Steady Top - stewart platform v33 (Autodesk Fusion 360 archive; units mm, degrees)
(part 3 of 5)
sketch "Sketch39" plane through (0, 0, 60.538) normal (0, 0, -1) x axis (1, 0, 0)
  curve K1 (-57.6704, 6.1748) -> (-51.1363, 4.8016)
  line L1 (-50.8174, 2.2182) -> (-57.6704, 6.1748)
  line L2 (-23.4876, -45.1182) -> (-50.8174, 2.2182)
  line L3 (-23.4876, -53.0314) -> (-23.4876, -45.1182)
  curve K2 (-21.4098, -46.6861) -> (-23.4876, -53.0314)
  curve K3 (-21.4098, -46.6861) -> (21.4098, -46.6861)
  curve K4 (23.4876, -53.0314) -> (21.4098, -46.6861)
  line L4 (23.4876, -45.1182) -> (23.4876, -53.0314)
  line L5 (50.8174, 2.2182) -> (23.4876, -45.1182)
  line L6 (57.6704, 6.1748) -> (50.8174, 2.2182)
  curve K5 (51.1363, 4.8016) -> (57.6704, 6.1748)
  curve K6 (51.1363, 4.8016) -> (28.8711, 42.469)
  curve K7 (28.8711, 42.469) -> (33.2215, 47.543)
  curve K8 (33.2215, 47.543) -> (34.8563, 49.4246)
  line L7 (-34.0436, 49.4926) -> (34.0436, 49.4926)
  curve K9 (-34.8563, 49.4246) -> (-33.2215, 47.543)
  line L8 (19.9564, 46.6037) -> (-34.0436, 46.6037)
  line L9 (21.9564, -34.3963) -> (21.9564, 44.6037)
  line L10 (-9.0436, -36.3963) -> (19.9564, -36.3963)
  line L11 (-11.0436, -20.9963) -> (-11.0436, -34.3963)
  line L12 (-31.0436, -18.3963) -> (-13.6436, -18.3963)
  line L13 (-33.0436, 2.6037) -> (-33.0436, -16.3963)
  line L14 (-11.6436, 4.6037) -> (-31.0436, 4.6037)
  line L15 (-9.0436, 11.0037) -> (-9.0436, 7.2037)
  line L16 (-34.0436, 13.6037) -> (-11.6436, 13.6037)
  line L17 (-36.0436, 36.6685) -> (-36.0436, 15.6037)
  curve K10 (-36.0436, 36.6685) -> (-51.1363, 4.8016)
  line L18 (-32.1129, 44.8573) -> (-36.65, 41.1209)
  line L19 (-7.0436, 45.9249) -> (-32.1129, 44.8573)
  line L20 (15.1267, 40.5871) -> (-7.0436, 45.9249)
  line L21 (21.9564, 13.0084) -> (15.1267, 40.5871)
  line L22 (27.9374, 13.0084) -> (21.9564, 13.0084)
  line L23 (27.3147, 47.8821) -> (27.9374, 13.0084)
  line L24 (-36.2006, 47.543) -> (27.3147, 47.8821)
  line L25 (-38.5136, 43.2045) -> (-36.2006, 47.543)
  line L26 (-36.65, 41.1209) -> (-38.5136, 43.2045)
  line L27 (11.3178, -29.1242) -> (19.9331, 23.7985)
  line L28 (-0.6206, -29.1242) -> (11.3178, -29.1242)
  line L29 (-11.8052, -19.1578) -> (-0.6206, -29.1242)
  arc A1 centre (34.0436, 44.6037) radius 4.8889 clockwise from (34.0436, 49.4926) to (34.8563, 49.4246)
  arc A2 centre (-34.0436, 44.6037) radius 4.8889 clockwise from (-34.8563, 49.4246) to (-34.0436, 49.4926)
  arc A3 centre (0, 0) radius 58 clockwise from (-34.656, 46.5076) to (-33.2215, 47.543)
  arc A4 centre (-34.0436, 44.6037) radius 2 clockwise from (-34.656, 46.5076) to (-34.0436, 46.6037)
  arc A5 centre (19.9564, 44.6037) radius 2 clockwise from (19.9564, 46.6037) to (21.9564, 44.6037)
  arc A6 centre (19.9564, -34.3963) radius 2 clockwise from (21.9564, -34.3963) to (19.9564, -36.3963)
  arc A7 centre (-9.0436, -34.3963) radius 2 clockwise from (-9.0436, -36.3963) to (-11.0436, -34.3963)
  arc A8 centre (-13.6436, -20.9963) radius 2.6 clockwise from (-13.6436, -18.3963) to (-11.0436, -20.9963)
  arc A9 centre (-31.0436, -16.3963) radius 2 clockwise from (-31.0436, -18.3963) to (-33.0436, -16.3963)
  arc A10 centre (-31.0436, 2.6037) radius 2 clockwise from (-33.0436, 2.6037) to (-31.0436, 4.6037)
  arc A11 centre (-11.6436, 7.2037) radius 2.6 clockwise from (-9.0436, 7.2037) to (-11.6436, 4.6037)
  arc A12 centre (-11.6436, 11.0037) radius 2.6 clockwise from (-11.6436, 13.6037) to (-9.0436, 11.0037)
  arc A13 centre (-34.0436, 15.6037) radius 2 clockwise from (-34.0436, 13.6037) to (-36.0436, 15.6037)
  point P58 (21.9564, 13.0084)
  point P66 (-11.8052, -19.1578)
  coincident L9 P58
  perpendicular L9 L22
  perpendicular L9 L28
  midpoint A8 P66
extrude "Extrude33" add sketch "Sketch39" profile of K9 A3 A4 L8 A5 L9 A6 L10 A7 L11 A8 L18 L19 L20 L21 L24 L25 L26 L27 L28 L29 against normal blind 2.5
component_insert "Component Insert19"
sketch "Sketch40" plane through (0, 0, -18.75) normal (0, 0, -1) x axis (1, 0, 0)
  line L1 (-50.6551, -0.2628) -> (-40.5926, -17.6915)
  line L2 (-41.6918, 4.9122) -> (-50.6551, -0.2628)
  line L3 (-31.6293, -12.5165) -> (-41.6918, 4.9122)
  line L4 (-40.5926, -17.6915) -> (-31.6293, -12.5165)
  line L5 (-26.6543, -21.1335) -> (-35.6176, -26.3085)
  line L6 (-16.5918, -38.5622) -> (-26.6543, -21.1335)
  line L7 (-25.5551, -43.7372) -> (-16.5918, -38.5622)
  line L8 (-35.6176, -26.3085) -> (-25.5551, -43.7372)
  line L9 (-4.975, 44) -> (-25.1, 44)
  line L10 (-4.975, 33.65) -> (-4.975, 44)
  line L11 (-25.1, 33.65) -> (-4.975, 33.65)
  line L12 (-25.1, 44) -> (-25.1, 33.65)
  line L13 (25.1, 44) -> (4.975, 44)
  line L14 (25.1, 33.65) -> (25.1, 44)
  line L15 (4.975, 33.65) -> (25.1, 33.65)
  line L16 (4.975, 44) -> (4.975, 33.65)
  line L17 (-9.7616, -40.3924) -> (-16.0102, -44)
  line L18 (-39.8616, 11.7424) -> (-9.7616, -40.3924)
  line L19 (-46.1102, 8.1347) -> (-39.8616, 11.7424)
  line L20 (-30.1, 35.8653) -> (-46.1102, 8.1347)
  line L21 (-30.1, 28.65) -> (-30.1, 35.8653)
  line L22 (30.1, 28.65) -> (-30.1, 28.65)
  line L23 (30.1, 35.8653) -> (30.1, 28.65)
  line L24 (46.1102, 8.1347) -> (30.1, 35.8653)
  line L25 (39.8616, 11.7424) -> (46.1102, 8.1347)
  line L26 (9.7616, -40.3924) -> (39.8616, 11.7424)
  line L27 (16.0102, -44) -> (9.7616, -40.3924)
  line L28 (-16.0102, -44) -> (16.0102, -44)
  line L29 (40.5926, -17.6915) -> (50.6551, -0.2628)
  line L30 (31.6293, -12.5165) -> (40.5926, -17.6915)
  line L31 (41.6918, 4.9122) -> (31.6293, -12.5165)
  line L32 (50.6551, -0.2628) -> (41.6918, 4.9122)
  line L33 (16.5918, -38.5622) -> (25.5551, -43.7372)
  line L34 (26.6543, -21.1335) -> (16.5918, -38.5622)
  line L35 (35.6176, -26.3085) -> (26.6543, -21.1335)
  line L36 (25.5551, -43.7372) -> (35.6176, -26.3085)
  line L37 (78.9466, 12.9395) -> (28.2673, -74.8395)
  line L38 (-50.6793, 61.9) -> (50.6793, 61.9)
  line L39 (-28.2673, -74.8395) -> (-78.9466, 12.9395)
  line L40 (121.7393, 0) -> (-121.7393, 0)
  line L41 (121.7393, 253.3747) -> (121.7393, 0)
  line L42 (-121.7393, 253.3747) -> (121.7393, 253.3747)
  line L43 (-121.7393, 0) -> (-121.7393, 253.3747)
  line L44 (121.7393, 253.3747) -> (-121.7393, 0)
  line L45 (-121.7393, 253.3747) -> (121.7393, 0)
  line L46 (41.9005, 165.7123) -> (-23.0995, 165.7123)
  arc A1 centre (0, 0) radius 80 clockwise from (28.2673, -74.8395) to (-28.2673, -74.8395)
  arc A2 centre (0, 0) radius 80 clockwise from (50.6793, 61.9) to (78.9466, 12.9395)
  arc A3 centre (0, 0) radius 80 clockwise from (-78.9466, 12.9395) to (-50.6793, 61.9)
  circle C1 centre (0, 0) radius 121.7393
  circle C2 centre (-23.0995, 165.7123) radius 2
  circle C3 centre (41.9005, 165.7123) radius 2
  point P1 (0, 0)
  point P45 (0, 0)
  point P50 (0, 126.6874)
  point P46 (-121.7393, 0)
  coincident P1 P45
  horizontal L40
  perpendicular L40 L41
  parallel L40 L42
  parallel L41 L43
  coincident L44 P50
  coincident L45 P50
  coincident C1 P46
extrude "Extrude34" new body sketch "Sketch40" profile of A1 L37 A2 L38 A3 L39 C1 L40 L41 L42 L43 L46 C2 C3 along normal blind 5
sketch "Sketch41" plane through (0, 0, -18.75) normal (0, 0, 1) x axis (1, 0, 0)
  line L1 (-28.2673, 74.8395) -> (-78.9466, -12.9395)
  line L2 (-50.6793, -61.9) -> (50.6793, -61.9)
  line L3 (78.9466, -12.9395) -> (28.2673, 74.8395)
  line L4 (-121.7393, -253.3747) -> (-121.7393, 0)
  line L5 (121.7393, 0) -> (121.7393, -253.3747)
  line L6 (121.7393, -253.3747) -> (-121.7393, -253.3747)
  circle C1 centre (-23.0995, -165.7123) radius 2
  arc A1 centre (0, 0) radius 80 clockwise from (-50.6793, -61.9) to (-78.9466, -12.9395)
  arc A2 centre (0, 0) radius 80 clockwise from (78.9466, -12.9395) to (50.6793, -61.9)
  arc A3 centre (0, 0) radius 80 clockwise from (-28.2673, 74.8395) to (28.2673, 74.8395)
  circle C2 centre (41.9005, -165.7123) radius 2
  arc A4 centre (0, 0) radius 121.7393 clockwise from (-121.7393, 0) to (121.7393, 0)
fillet "Fillet10" radius 27.954
sketch "Sketch42" plane through (0, 0, -23.75) normal (0, 0, 1) x axis (1, 0, 0)
  line L1 (-28.2673, 74.8395) -> (-78.9466, -12.9395)
  line L2 (-50.6793, -61.9) -> (50.6793, -61.9)
  line L3 (78.9466, -12.9395) -> (28.2673, 74.8395)
  line L4 (93.7853, -253.3747) -> (-93.7853, -253.3747)
  line L5 (-121.7393, -225.4207) -> (-121.7393, 0)
  line L6 (121.7393, 0) -> (121.7393, -225.4207)
  line L7 (93.7853, -278.3747) -> (-93.7853, -278.3747)
  line L8 (146.7393, 0) -> (146.7393, -225.4207)
  line L9 (-146.7393, -225.4207) -> (-146.7393, 0)
  line L10 (-78.9466, -12.9395) -> (-28.2673, 74.8395)
  line L11 (50.6793, -61.9) -> (-50.6793, -61.9)
  line L12 (28.2673, 74.8395) -> (78.9466, -12.9395)
  line L13 (-93.7853, -253.3747) -> (93.7853, -253.3747)
  line L14 (-121.7393, 0) -> (-121.7393, -225.4207)
  line L15 (121.7393, -225.4207) -> (121.7393, 0)
  circle C1 centre (-23.0995, -165.7123) radius 2
  arc A1 centre (0, 0) radius 80 clockwise from (-50.6793, -61.9) to (-78.9466, -12.9395)
  arc A2 centre (0, 0) radius 80 clockwise from (78.9466, -12.9395) to (50.6793, -61.9)
  arc A3 centre (0, 0) radius 80 clockwise from (-28.2673, 74.8395) to (28.2673, 74.8395)
  circle C2 centre (41.9005, -165.7123) radius 2
  arc A4 centre (93.7853, -225.4207) radius 27.954 clockwise from (121.7393, -225.4207) to (93.7853, -253.3747)
  arc A5 centre (-93.7853, -225.4207) radius 27.954 clockwise from (-93.7853, -253.3747) to (-121.7393, -225.4207)
  arc A6 centre (0, 0) radius 121.7393 clockwise from (-121.7393, 0) to (121.7393, 0)
  circle C3 centre (41.9005, -165.7123) radius 7
  circle C4 centre (-23.0995, -165.7123) radius 7
  arc A7 centre (93.7853, -225.4207) radius 52.954 clockwise from (146.7393, -225.4207) to (93.7853, -278.3747)
  arc A8 centre (0, 0) radius 146.7393 clockwise from (-146.7393, 0) to (146.7393, 0)
  arc A9 centre (-93.7853, -225.4207) radius 52.954 clockwise from (-93.7853, -278.3747) to (-146.7393, -225.4207)
  circle C5 centre (41.9005, -165.7123) radius 2
  arc A10 centre (0, 0) radius 80 clockwise from (-50.6793, -61.9) to (-78.9466, -12.9395)
  arc A11 centre (0, 0) radius 80 clockwise from (78.9466, -12.9395) to (50.6793, -61.9)
  arc A12 centre (0, 0) radius 80 clockwise from (-28.2673, 74.8395) to (28.2673, 74.8395)
  circle C6 centre (-23.0995, -165.7123) radius 2
  arc A13 centre (93.7853, -225.4207) radius 27.954 clockwise from (121.7393, -225.4207) to (93.7853, -253.3747)
  arc A14 centre (-93.7853, -225.4207) radius 27.954 clockwise from (-93.7853, -253.3747) to (-121.7393, -225.4207)
  arc A15 centre (0, 0) radius 121.7393 clockwise from (-121.7393, 0) to (121.7393, 0)
  dimension "d334" = 25
  dimension "d335" = 5
  dimension "d336" = 5
extrude "Extrude35" new body sketch "Sketch42" profile of L1 A1 L2 A2 L3 A3 A4 L4 A5 L5 A6 L6 A8 A7 L9 A9 L8 L7 C3 C4 L10 A10 L11 A11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 against normal blind 5 bodies "Base 1"
sketch "Sketch43" plane through (0, 0, -28.75) normal (0, 0, -1) x axis (1, 0, 0)
  line L1 (-146.7393, 0) -> (-146.7393, 225.4207)
  line L2 (146.7393, 225.4207) -> (146.7393, 0)
  line L3 (-93.7853, 278.3747) -> (93.7853, 278.3747)
  line L4 (-50.6551, -0.2628) -> (-40.5926, -17.6915)
  line L5 (-41.6918, 4.9122) -> (-50.6551, -0.2628)
  line L6 (-31.6293, -12.5165) -> (-41.6918, 4.9122)
  line L7 (-40.5926, -17.6915) -> (-31.6293, -12.5165)
  line L8 (-26.6543, -21.1335) -> (-35.6176, -26.3085)
  line L9 (-16.5918, -38.5622) -> (-26.6543, -21.1335)
  line L10 (-25.5551, -43.7372) -> (-16.5918, -38.5622)
  line L11 (-35.6176, -26.3085) -> (-25.5551, -43.7372)
  line L12 (-4.975, 44) -> (-25.1, 44)
  line L13 (-4.975, 33.65) -> (-4.975, 44)
  line L14 (-25.1, 33.65) -> (-4.975, 33.65)
  line L15 (-25.1, 44) -> (-25.1, 33.65)
  line L16 (25.1, 44) -> (4.975, 44)
  line L17 (25.1, 33.65) -> (25.1, 44)
  line L18 (4.975, 33.65) -> (25.1, 33.65)
  line L19 (4.975, 44) -> (4.975, 33.65)
  line L20 (-9.7616, -40.3924) -> (-16.0102, -44)
  line L21 (-39.8616, 11.7424) -> (-9.7616, -40.3924)
  line L22 (-46.1102, 8.1347) -> (-39.8616, 11.7424)
  line L23 (-30.1, 35.8653) -> (-46.1102, 8.1347)
  line L24 (-30.1, 28.65) -> (-30.1, 35.8653)
  line L25 (30.1, 28.65) -> (-30.1, 28.65)
  line L26 (30.1, 35.8653) -> (30.1, 28.65)
  line L27 (46.1102, 8.1347) -> (30.1, 35.8653)
  line L28 (39.8616, 11.7424) -> (46.1102, 8.1347)
  line L29 (9.7616, -40.3924) -> (39.8616, 11.7424)
  line L30 (16.0102, -44) -> (9.7616, -40.3924)
  line L31 (-16.0102, -44) -> (16.0102, -44)
  line L32 (40.5926, -17.6915) -> (50.6551, -0.2628)
  line L33 (31.6293, -12.5165) -> (40.5926, -17.6915)
  line L34 (41.6918, 4.9122) -> (31.6293, -12.5165)
  line L35 (50.6551, -0.2628) -> (41.6918, 4.9122)
  line L36 (16.5918, -38.5622) -> (25.5551, -43.7372)
  line L37 (26.6543, -21.1335) -> (16.5918, -38.5622)
  line L38 (35.6176, -26.3085) -> (26.6543, -21.1335)
  line L39 (25.5551, -43.7372) -> (35.6176, -26.3085)
  line L40 (78.9466, 12.9395) -> (28.2673, -74.8395)
  line L41 (-50.6793, 61.9) -> (50.6793, 61.9)
  line L42 (-28.2673, -74.8395) -> (-78.9466, 12.9395)
  line L43 (0, 76.9) -> (0, 61.9)
  line L44 (0, -95) -> (0, -80)
  circle C1 centre (-23.0995, 165.7123) radius 7
  circle C2 centre (41.9005, 165.7123) radius 7
  arc A1 centre (-93.7853, 225.4207) radius 52.954 clockwise from (-146.7393, 225.4207) to (-93.7853, 278.3747)
  arc A2 centre (0, 0) radius 146.7393 clockwise from (146.7393, 0) to (-146.7393, 0)
  arc A3 centre (93.7853, 225.4207) radius 52.954 clockwise from (93.7853, 278.3747) to (146.7393, 225.4207)
  arc A4 centre (0, 0) radius 80 clockwise from (28.2673, -74.8395) to (-28.2673, -74.8395)
  arc A5 centre (0, 0) radius 80 clockwise from (50.6793, 61.9) to (78.9466, 12.9395)
  arc A6 centre (0, 0) radius 80 clockwise from (-78.9466, 12.9395) to (-50.6793, 61.9)
  point P56 (0, 61.9)
  point P58 (0, -80)
  point P57 (0, 76.9)
  point P59 (0, -95)
  midpoint L41 P56
  perpendicular L41 L43
  midpoint A4 P58
  perpendicular L41 L44
  dimension "d339" distance P56 P57 = 15
  dimension "d340" distance P58 P59 = 15
hole "Hole2" HoleDepth 10 HoleDiameter 4 TipAngle 180 CBDepth 5 CBDiameter 24
circular_pattern "C-Pattern4" TotalAngle 360
sketch "Sketch44" plane through (0, 0, -28.75) normal (0, 0, -1) x axis (1, 0, 0)
  line L1 (-146.7393, 0) -> (-146.7393, 225.4207)
  line L2 (146.7393, 225.4207) -> (146.7393, 0)
  line L3 (-93.7853, 278.3747) -> (93.7853, 278.3747)
  line L4 (121.7393, 225.4207) -> (121.7393, 0)
  line L5 (-93.7853, 253.3747) -> (93.7853, 253.3747)
  line L6 (-121.7393, 0) -> (-121.7393, 225.4207)
  circle C1 centre (-82.2724, 47.5) radius 12
  circle C2 centre (82.2724, 47.5) radius 12
  circle C3 centre (0, -95) radius 12
  circle C4 centre (-23.0995, 165.7123) radius 7
  circle C5 centre (41.9005, 165.7123) radius 7
  arc A1 centre (-93.7853, 225.4207) radius 52.954 clockwise from (-146.7393, 225.4207) to (-93.7853, 278.3747)
  arc A2 centre (0, 0) radius 146.7393 clockwise from (146.7393, 0) to (-146.7393, 0)
  arc A3 centre (93.7853, 225.4207) radius 52.954 clockwise from (93.7853, 278.3747) to (146.7393, 225.4207)
  arc A4 centre (0, 0) radius 121.7393 clockwise from (121.7393, 0) to (-121.7393, 0)
  arc A5 centre (93.7853, 225.4207) radius 27.954 clockwise from (93.7853, 253.3747) to (121.7393, 225.4207)
  arc A6 centre (-93.7853, 225.4207) radius 27.954 clockwise from (-121.7393, 225.4207) to (-93.7853, 253.3747)
sketch "Sketch45" plane through (0, 0, -18.75) normal (0, 0, 1) x axis (-1, 0, 0)
  line L1 (-121.7393, 0) -> (-121.7393, 225.4207)
  line L2 (121.7393, 225.4207) -> (121.7393, 0)
  line L3 (-93.7853, 253.3747) -> (93.7853, 253.3747)
  line L4 (28.2673, -74.8395) -> (78.9466, 12.9395)
  line L5 (-78.9466, 12.9395) -> (-28.2673, -74.8395)
  line L6 (50.6793, 61.9) -> (-50.6793, 61.9)
  circle C1 centre (82.2724, 47.5) radius 2
  circle C2 centre (-82.2724, 47.5) radius 2
  circle C3 centre (0, -95) radius 2
  arc A1 centre (-93.7853, 225.4207) radius 27.954 clockwise from (-121.7393, 225.4207) to (-93.7853, 253.3747)
  arc A2 centre (0, 0) radius 121.7393 clockwise from (121.7393, 0) to (-121.7393, 0)
  arc A3 centre (93.7853, 225.4207) radius 27.954 clockwise from (93.7853, 253.3747) to (121.7393, 225.4207)
  circle C4 centre (-41.9005, 165.7123) radius 2
  arc A4 centre (0, 0) radius 80 clockwise from (28.2673, -74.8395) to (-28.2673, -74.8395)
  arc A5 centre (0, 0) radius 80 clockwise from (-78.9466, 12.9395) to (-50.6793, 61.9)
  arc A6 centre (0, 0) radius 80 clockwise from (50.6793, 61.9) to (78.9466, 12.9395)
  circle C5 centre (23.0995, 165.7123) radius 2
move "Move7"
position "Position22"
joint "Assemble12" alignAngle 0 alignOffsetX 0 alignOffsetY 0 alignOffsetZ 4.715
joint "Assemble13" alignAngle 100 alignOffsetX 0 alignOffsetY 0 alignOffsetZ -0.04
joint "Assemble14" alignAngle 90 alignOffsetX 0 alignOffsetY 0 alignOffsetZ 4.368
joint "Assemble15" alignAngle 0 alignOffsetX 0 alignOffsetY 0 alignOffsetZ -0.04
position "Position23"
sketch "Sketch46" plane through (0, 0, -18.75) normal (0, 0, 1) x axis (-1, 0, 0)
  line L1 (121.7393, 0) -> (121.7393, -225.4207)
  line L2 (-121.7393, -225.4207) -> (-121.7393, 0)
  line L3 (93.7853, -253.3747) -> (-93.7853, -253.3747)
  line L4 (-28.2673, 74.8395) -> (-78.9466, -12.9395)
  line L5 (78.9466, -12.9395) -> (28.2673, 74.8395)
  line L6 (-50.6793, -61.9) -> (50.6793, -61.9)
  line L7 (121.7393, -225.4207) -> (121.7393, 0)
  line L8 (-121.7393, 0) -> (-121.7393, -225.4207)
  line L9 (-93.7853, -253.3747) -> (93.7853, -253.3747)
  curve K1 (-23.0243, -187.6129) -> (-21.622, -184.7896)
  curve K2 (-24.0965, -184.2248) -> (-24.0581, -187.3769)
  curve K3 (41.9757, -187.6129) -> (43.378, -184.7896)
  curve K4 (40.9035, -184.2248) -> (40.9419, -187.3769)
  line L10 (-121.7393, 0) -> (-121.7393, -225.4207)
  line L11 (-121.7393, -225.4207) -> (-121.7393, 0)
  line L12 (-93.7853, -253.3747) -> (93.7853, -253.3747)
  line L13 (93.7853, -253.3747) -> (-93.7853, -253.3747)
  line L14 (121.7393, 0) -> (121.7393, -225.4207)
  line L15 (121.7393, -225.4207) -> (121.7393, 0)
  line L16 (50.6551, -0.2628) -> (40.5926, -17.6915)
  line L17 (41.6918, 4.9122) -> (50.6551, -0.2628)
  line L18 (31.6293, -12.5165) -> (41.6918, 4.9122)
  line L19 (40.5926, -17.6915) -> (31.6293, -12.5165)
  line L20 (26.6543, -21.1335) -> (35.6176, -26.3085)
  line L21 (16.5918, -38.5622) -> (26.6543, -21.1335)
  line L22 (25.5551, -43.7372) -> (16.5918, -38.5622)
  line L23 (35.6176, -26.3085) -> (25.5551, -43.7372)
  line L24 (4.975, 44) -> (25.1, 44)
  line L25 (4.975, 33.65) -> (4.975, 44)
  line L26 (25.1, 33.65) -> (4.975, 33.65)
  line L27 (25.1, 44) -> (25.1, 33.65)
  line L28 (-25.1, 44) -> (-4.975, 44)
  line L29 (-25.1, 33.65) -> (-25.1, 44)
  line L30 (-4.975, 33.65) -> (-25.1, 33.65)
  line L31 (-4.975, 44) -> (-4.975, 33.65)
  line L32 (9.7616, -40.3924) -> (16.0102, -44)
  line L33 (39.8616, 11.7424) -> (9.7616, -40.3924)
  line L34 (46.1102, 8.1347) -> (39.8616, 11.7424)
  line L35 (30.1, 35.8653) -> (46.1102, 8.1347)
  line L36 (30.1, 28.65) -> (30.1, 35.8653)
  line L37 (-30.1, 28.65) -> (30.1, 28.65)
  line L38 (-30.1, 35.8653) -> (-30.1, 28.65)
  line L39 (-46.1102, 8.1347) -> (-30.1, 35.8653)
  line L40 (-39.8616, 11.7424) -> (-46.1102, 8.1347)
  line L41 (-9.7616, -40.3924) -> (-39.8616, 11.7424)
  line L42 (-16.0102, -44) -> (-9.7616, -40.3924)
  line L43 (16.0102, -44) -> (-16.0102, -44)
  line L44 (-40.5926, -17.6915) -> (-50.6551, -0.2628)
  line L45 (-31.6293, -12.5165) -> (-40.5926, -17.6915)
  line L46 (-41.6918, 4.9122) -> (-31.6293, -12.5165)
  line L47 (-50.6551, -0.2628) -> (-41.6918, 4.9122)
  line L48 (-16.5918, -38.5622) -> (-25.5551, -43.7372)
  line L49 (-26.6543, -21.1335) -> (-16.5918, -38.5622)
  line L50 (-35.6176, -26.3085) -> (-26.6543, -21.1335)
  line L51 (-25.5551, -43.7372) -> (-35.6176, -26.3085)
  line L52 (-78.9466, 12.9395) -> (-28.2673, -74.8395)
  line L53 (50.6793, 61.9) -> (-50.6793, 61.9)
  line L54 (28.2673, -74.8395) -> (78.9466, 12.9395)
  line L55 (0, -44) -> (-97.1658, -187.2496)
  line L56 (2.4827, -45.684) -> (-94.6831, -188.9336)
  line L57 (-2.4827, -42.316) -> (-99.6485, -185.5655)
  circle C1 centre (-82.2724, -47.5) radius 2
  circle C2 centre (82.2724, -47.5) radius 2
  circle C3 centre (0, 95) radius 2
  arc A1 centre (93.7853, -225.4207) radius 27.954 clockwise from (121.7393, -225.4207) to (93.7853, -253.3747)
  arc A2 centre (0, 0) radius 121.7393 clockwise from (-121.7393, 0) to (121.7393, 0)
  arc A3 centre (-93.7853, -225.4207) radius 27.954 clockwise from (-93.7853, -253.3747) to (-121.7393, -225.4207)
  arc A4 centre (0, 0) radius 80 clockwise from (-28.2673, 74.8395) to (28.2673, 74.8395)
  arc A5 centre (0, 0) radius 80 clockwise from (78.9466, -12.9395) to (50.6793, -61.9)
  arc A6 centre (0, 0) radius 80 clockwise from (-50.6793, -61.9) to (-78.9466, -12.9395)
  circle C4 centre (-23.0995, -165.7123) radius 2
  circle C5 centre (41.9005, -165.7123) radius 2
  arc A7 centre (0, 0) radius 121.7393 clockwise from (-121.7393, 0) to (121.7393, 0)
  arc A8 centre (-93.7853, -225.4207) radius 27.954 clockwise from (-93.7853, -253.3747) to (-121.7393, -225.4207)
  arc A9 centre (93.7853, -225.4207) radius 27.954 clockwise from (121.7393, -225.4207) to (93.7853, -253.3747)
  arc A10 centre (-23.0995, -185.5595) radius 1.666 clockwise from (-24.0965, -184.2248) to (-21.622, -184.7896)
  arc A11 centre (-23.0995, -185.5595) radius 2.0548 clockwise from (-23.0243, -187.6129) to (-24.0581, -187.3769)
  arc A12 centre (41.9005, -185.5595) radius 1.666 clockwise from (40.9035, -184.2248) to (43.378, -184.7896)
  arc A13 centre (41.9005, -185.5595) radius 2.0548 clockwise from (41.9757, -187.6129) to (40.9419, -187.3769)
  arc A14 centre (0, 0) radius 121.7393 clockwise from (-121.7393, 0) to (121.7393, 0)
  arc A15 centre (0, 0) radius 121.7393 clockwise from (-121.7393, 0) to (121.7393, 0)
  arc A16 centre (-93.7853, -225.4207) radius 27.954 clockwise from (-93.7853, -253.3747) to (-121.7393, -225.4207)
  arc A17 centre (-93.7853, -225.4207) radius 27.954 clockwise from (-93.7853, -253.3747) to (-121.7393, -225.4207)
  arc A18 centre (93.7853, -225.4207) radius 27.954 clockwise from (121.7393, -225.4207) to (93.7853, -253.3747)
  arc A19 centre (93.7853, -225.4207) radius 27.954 clockwise from (121.7393, -225.4207) to (93.7853, -253.3747)
  circle C6 centre (41.9005, -185.5595) radius 2.1
  circle C7 centre (-23.0995, -185.5595) radius 2.1
  circle C8 centre (-97.1658, -187.2496) radius 3
  circle C9 centre (-21.5241, 0) radius 3.0256
  arc A20 centre (0, 0) radius 80 clockwise from (28.2673, -74.8395) to (-28.2673, -74.8395)
  arc A21 centre (0, 0) radius 80 clockwise from (-78.9466, 12.9395) to (-50.6793, 61.9)
  arc A22 centre (0, 0) radius 80 clockwise from (50.6793, 61.9) to (78.9466, 12.9395)
  point P58 (-97.1658, -187.2496)
  point P103 (-97.1658, -187.2496)
  point P104 (0, -44)
  concentric A12 C6
  concentric A10 C7
  equal C6 C7
  coincident P58 P103
  midpoint L43 P104
  dimension "d370" diameter C7 = 4.2
  dimension "d371" diameter C8 = 6
  dimension "d372" = 3
  dimension "d373" = -3
sketch "Sketch47" plane through (0, 0, 37.7) normal (0, 0, 1) x axis (-1, 0, 0)
  line L1 (38.8652, -28.1835) -> (43.8402, -19.5665)
  line L2 (38.8869, -28.196) -> (38.8652, -28.1835)
  line L3 (28.8244, -45.6247) -> (38.8869, -28.196)
  line L4 (28.8027, -45.6122) -> (28.8244, -45.6247)
  line L5 (18.6803, -63.1448) -> (28.8027, -45.6122)
  line L6 (-28.8027, -45.6122) -> (-18.6803, -63.1448)
  line L7 (-28.8244, -45.6247) -> (-28.8027, -45.6122)
  line L8 (-38.8869, -28.196) -> (-28.8244, -45.6247)
  line L9 (-38.8652, -28.1835) -> (-38.8869, -28.196)
  line L10 (-43.8402, -19.5665) -> (-38.8652, -28.1835)
  line L11 (-43.8619, -19.579) -> (-43.8402, -19.5665)
  line L12 (-53.9244, -2.1503) -> (-43.8619, -19.579)
  line L13 (-53.9027, -2.1378) -> (-53.9244, -2.1503)
  line L14 (-64.0252, 15.3948) -> (-53.9027, -2.1378)
  line L15 (-25.1, 47.75) -> (-45.3449, 47.75)
  line L16 (-25.1, 47.775) -> (-25.1, 47.75)
  line L17 (-4.975, 47.775) -> (-25.1, 47.775)
  line L18 (-4.975, 47.75) -> (-4.975, 47.775)
  line L19 (4.975, 47.75) -> (-4.975, 47.75)
  line L20 (4.975, 47.775) -> (4.975, 47.75)
  line L21 (25.1, 47.775) -> (4.975, 47.775)
  line L22 (25.1, 47.75) -> (25.1, 47.775)
  line L23 (45.3449, 47.75) -> (25.1, 47.75)
  line L24 (53.9027, -2.1378) -> (64.0252, 15.3948)
  line L25 (53.9244, -2.1503) -> (53.9027, -2.1378)
  line L26 (43.8619, -19.579) -> (53.9244, -2.1503)
  line L27 (43.8402, -19.5665) -> (43.8619, -19.579)
  line L28 (78.9466, 12.9395) -> (28.2673, -74.8395)
  line L29 (-50.6793, 61.9) -> (50.6793, 61.9)
  line L30 (-28.2673, -74.8395) -> (-78.9466, 12.9395)
  line L31 (-48.4891, 55.9) -> (48.4891, 55.9)
  line L32 (-24.1663, -69.9428) -> (-72.6554, 14.0428)
  line L33 (72.6554, 14.0428) -> (24.1663, -69.9428)
  arc A1 centre (0, 0) radius 65.85 clockwise from (18.6803, -63.1448) to (-18.6803, -63.1448)
  arc A2 centre (0, 0) radius 65.85 clockwise from (-64.0252, 15.3948) to (-45.3449, 47.75)
  arc A3 centre (0, 0) radius 65.85 clockwise from (45.3449, 47.75) to (64.0252, 15.3948)
  arc A4 centre (0, 0) radius 80 clockwise from (28.2673, -74.8395) to (-28.2673, -74.8395)
  arc A5 centre (0, 0) radius 80 clockwise from (50.6793, 61.9) to (78.9466, 12.9395)
  arc A6 centre (0, 0) radius 80 clockwise from (-78.9466, 12.9395) to (-50.6793, 61.9)
  arc A7 centre (0, 0) radius 74 clockwise from (40.5511, 61.9) to (73.8825, 4.1683)
  arc A8 centre (0, 0) radius 74 clockwise from (-73.8825, 4.1683) to (-40.5511, 61.9)
  arc A9 centre (0, 0) radius 74 clockwise from (33.3314, -66.0683) to (-33.3314, -66.0683)
  point P45 (-24.1663, -69.9428)
  point P48 (-33.3314, -66.0683)
  point P47 (24.1663, -69.9428)
  point P49 (33.3314, -66.0683)
  point P40 (72.6554, 14.0428)
  point P50 (73.8825, 4.1683)
  point P41 (48.4891, 55.9)
  point P51 (40.5511, 61.9)
  point P44 (-72.6554, 14.0428)
  point P52 (-73.8825, 4.1683)
  point P42 (-48.4891, 55.9)
  point P53 (-40.5511, 61.9)
  concentric A5 A7
  concentric A6 A8
  concentric A4 A9
  coincident P45 A9
  coincident L30 P48
  coincident P47 A9
  coincident L28 P49
  coincident P40 A7
  coincident L28 P50
  coincident P41 A7
  coincident L29 P51
  coincident P44 A8
  coincident L30 P52
  coincident P42 A8
  coincident L29 P53
extrude "Extrude1" cut sketch "Sketch47" profile of A4 L28 A5 L29 A6 L30 A7 A9 A8 against normal blind 7
sketch "Sketch48" plane through (0, 0, 33.7) normal (0, 0, 1) x axis (-1, 0, 0)
  line L1 (12.909, -29.3521) -> (12.909, 20.5494)
  line L2 (-6.4713, -35.4654) -> (6.7957, -35.4654)
  line L3 (-12.491, 20.7277) -> (-12.491, -29.4458)
  line L4 (6.6939, 26.7646) -> (-6.454, 26.7646)
  line L5 (-53.9027, -2.1378) -> (-64.0252, 15.3948)
  line L6 (-41.6918, 4.9122) -> (-53.9027, -2.1378)
  line L7 (-39.1605, 0.528) -> (-41.6918, 4.9122)
  line L8 (-34.8304, 3.028) -> (-39.1605, 0.528)
  line L9 (-29.8304, -5.6323) -> (-34.8304, 3.028)
  line L10 (-34.1605, -8.1323) -> (-29.8304, -5.6323)
  line L11 (-31.6293, -12.5165) -> (-34.1605, -8.1323)
  line L12 (-43.8402, -19.5665) -> (-31.6293, -12.5165)
  line L13 (-38.8652, -28.1835) -> (-43.8402, -19.5665)
  line L14 (-26.6543, -21.1335) -> (-38.8652, -28.1835)
  line L15 (-24.123, -25.5177) -> (-26.6543, -21.1335)
  line L16 (-19.7929, -23.0177) -> (-24.123, -25.5177)
  line L17 (-14.7929, -31.678) -> (-19.7929, -23.0177)
  line L18 (-19.123, -34.178) -> (-14.7929, -31.678)
  line L19 (-16.5918, -38.5622) -> (-19.123, -34.178)
  line L20 (-28.8027, -45.6122) -> (-16.5918, -38.5622)
  line L21 (-18.6803, -63.1448) -> (-28.8027, -45.6122)
  line L22 (28.8027, -45.6122) -> (18.6803, -63.1448)
  line L23 (16.5918, -38.5622) -> (28.8027, -45.6122)
  line L24 (19.123, -34.178) -> (16.5918, -38.5622)
  line L25 (14.7929, -31.678) -> (19.123, -34.178)
  line L26 (19.7929, -23.0177) -> (14.7929, -31.678)
  line L27 (24.123, -25.5177) -> (19.7929, -23.0177)
  line L28 (26.6543, -21.1335) -> (24.123, -25.5177)
  line L29 (38.8652, -28.1835) -> (26.6543, -21.1335)
  line L30 (43.8402, -19.5665) -> (38.8652, -28.1835)
  line L31 (31.6293, -12.5165) -> (43.8402, -19.5665)
  line L32 (34.1605, -8.1323) -> (31.6293, -12.5165)
  line L33 (29.8304, -5.6323) -> (34.1605, -8.1323)
  line L34 (34.8304, 3.028) -> (29.8304, -5.6323)
  line L35 (39.1605, 0.528) -> (34.8304, 3.028)
  line L36 (41.6918, 4.9122) -> (39.1605, 0.528)
  line L37 (53.9027, -2.1378) -> (41.6918, 4.9122)
  line L38 (64.0252, 15.3948) -> (53.9027, -2.1378)
  line L39 (25.1, 47.75) -> (45.3449, 47.75)
  line L40 (25.1, 33.65) -> (25.1, 47.75)
  line L41 (20.0375, 33.65) -> (25.1, 33.65)
  line L42 (20.0375, 28.65) -> (20.0375, 33.65)
  line L43 (10.0375, 28.65) -> (20.0375, 28.65)
  line L44 (10.0375, 33.65) -> (10.0375, 28.65)
  line L45 (4.975, 33.65) -> (10.0375, 33.65)
  line L46 (4.975, 47.75) -> (4.975, 33.65)
  line L47 (-4.975, 47.75) -> (4.975, 47.75)
  line L48 (-4.975, 33.65) -> (-4.975, 47.75)
  line L49 (-10.0375, 33.65) -> (-4.975, 33.65)
  line L50 (-10.0375, 28.65) -> (-10.0375, 33.65)
  line L51 (-20.0375, 28.65) -> (-10.0375, 28.65)
  line L52 (-20.0375, 33.65) -> (-20.0375, 28.65)
  line L53 (-25.1, 33.65) -> (-20.0375, 33.65)
  line L54 (-25.1, 47.75) -> (-25.1, 33.65)
  line L55 (-45.3449, 47.75) -> (-25.1, 47.75)
  circle C1 centre (9.734, -32.2904) radius 1.25
  circle C2 centre (9.734, 23.5896) radius 1.25
  circle C3 centre (-9.316, 23.5896) radius 1.25
  circle C4 centre (-9.316, -32.2904) radius 1.25
  arc A1 centre (11.909, 20.5494) radius 1 clockwise from (11.4342, 21.4295) to (12.909, 20.5494)
  arc A2 centre (11.909, -29.3521) radius 1 clockwise from (12.909, -29.3521) to (11.4453, -30.2381)
  arc A3 centre (10.1521, -32.7085) radius 2.7884 clockwise from (7.6817, -34.0017) to (11.4453, -30.2381)
  arc A4 centre (6.7957, -34.4654) radius 1 clockwise from (7.6817, -34.0017) to (6.7957, -35.4654)
  arc A5 centre (-6.4713, -34.4654) radius 1 clockwise from (-6.4713, -35.4654) to (-7.363, -34.0127)
  arc A6 centre (-9.8005, -32.7749) radius 2.7338 clockwise from (-11.0382, -30.3374) to (-7.363, -34.0127)
  arc A7 centre (-11.491, -29.4458) radius 1 clockwise from (-11.0382, -30.3374) to (-12.491, -29.4458)
  arc A8 centre (-11.491, 20.7277) radius 1 clockwise from (-12.491, 20.7277) to (-11.0361, 21.6182)
  arc A9 centre (-9.7881, 24.0617) radius 2.7438 clockwise from (-7.3446, 25.3097) to (-11.0361, 21.6182)
  arc A10 centre (-6.454, 25.7646) radius 1 clockwise from (-7.3446, 25.3097) to (-6.454, 26.7646)
  arc A11 centre (6.6939, 25.7646) radius 1 clockwise from (6.6939, 26.7646) to (7.5739, 25.2897)
  arc A12 centre (10.0812, 23.9368) radius 2.849 clockwise from (11.4342, 21.4295) to (7.5739, 25.2897)
  arc A13 centre (0, 0) radius 65.85 clockwise from (-64.0252, 15.3948) to (-45.3449, 47.75)
  arc A14 centre (0, 0) radius 65.85 clockwise from (18.6803, -63.1448) to (-18.6803, -63.1448)
  arc A15 centre (0, 0) radius 65.85 clockwise from (45.3449, 47.75) to (64.0252, 15.3948)
  circle C5 centre (-20.2912, -4.3991) radius 2.75
  dimension "d377" diameter C5 = 5.5
extrude "Extrude2" cut sketch "Sketch48" profile of C5 against normal blind 3
step "00000000-0000-0000-0000-000000000000" TotalAngle 360
mirror_component "MirrorComponent2"
derived_instance "DerivedInstance8"
derived_instance "DerivedInstance1"
step "00000000-0000-0000-0000-000000000000" TotalAngle 360
extrude "Extrude36" new body sketch "Sketch46" profile of C1 C2 C3 A1 L1 A2 L2 A3 L3 L4 A4 L5 A5 L6 A6 C4 C5 L7 A7 L8 A8 L9 A9 L10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 against normal blind 5 bodies "Base 2"
component_from_bodies "Body->Comp7"
component_from_bodies "Body->Comp8"
component_from_bodies "Body->Comp9"
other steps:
derived_base_feature "Derived Base Feature1" bodies "Lock Base"
derived_base_feature "Derived Base Feature1"
base_feature "Base Feature1" bodies "Base 2"
base_feature "Base Feature1" bodies "Base 1"
base_feature "Base Feature1" bodies "PCB Mount"
base_feature "Base Feature1"
base_feature "Base Feature1"
base_feature "Base Feature1"
base_feature "Base Feature1"
base_feature "Base Feature1"
derived_base_feature "Derived Base Feature1"
derived_base_feature "Derived Base Feature1"
derived_base_feature "Derived Base Feature1"
derived_base_feature "Derived Base Feature1"
derived_base_feature "Derived Base Feature1"
derived_base_feature "Derived Base Feature1"
base_feature "Base Feature1"
derived_base_feature "Derived Base Feature1"
base_feature "Base Feature1"
base_feature "Base Feature1"
chamfer "Chamfer1" distance 0.4 named "d35_1"
thread "Thread2" ThreadOffset 0 named "d38_1" ThreadLength 10 named "d39_1"
base_feature "Base Feature1"
base_feature "Base Feature2"
base_feature "Base Feature3"
create_component "CreateComponent2"
joint_origin "JointOrigin1"
create_component "CreateComponent1"
remove_body "RemoveBody1"
create_component "CreateComponent2"
create_component "CreateComponent3"
remove_body "RemoveBody2"
joint_origin "JointOrigin1"
joint_origin "JointOrigin1"
joint_origin "JointOrigin1"
joint_origin "JointOrigin2"
create_component "CreateComponent5"
create_component "CreateComponent6"
joint_origin "JointOrigin2"
joint_origin "JointOrigin3"
create_component "CreateComponent7"
create_component "CreateComponent8"
create_component "CreateComponent9"
joint_origin "JointOrigin2"
joint_origin "JointOrigin2"
joint_origin "JointOrigin4"
joint_origin "JointOrigin3"
joint_origin "JointOrigin3"
joint_origin "JointOrigin5"
joint_origin "JointOrigin4"
joint_origin "JointOrigin3"
create_component "CreateComponent10"
joint_origin "JointOrigin1"
joint_origin "JointOrigin3"
create_component "CreateComponent11"
remove_body "RemoveBody1"
create_component "CreateComponent12"
remove_body "RemoveBody2"
create_component "CreateComponent13"
create_component "CreateComponent14"
create_component "CreateComponent15"
create_component "CreateComponent16"
create_component "CreateComponent17"
create_component "CreateComponent18"
create_component "CreateComponent19"
create_component "CreateComponent20"
remove_body "RemoveBody3"
create_component "CreateComponent21"
remove_body "RemoveBody4"
create_component "CreateComponent22"
remove_body "RemoveBody5"
create_component "CreateComponent23"
remove_body "RemoveBody6"
create_component "CreateComponent24"
joint_origin "JointOrigin4"
joint_origin "JointOrigin5"
joint_origin "JointOrigin6"
joint_origin "JointOrigin5"
joint_origin "JointOrigin3"
joint_origin "JointOrigin6"
joint_origin "JointOrigin8"
joint_origin "JointOrigin6"
joint_origin "JointOrigin7"
create_component "CreateComponent25"
create_component "CreateComponent26"
create_component "CreateComponent27"
remove_body "RemoveBody7"
create_component "CreateComponent28"
remove_body "RemoveBody8"
create_component "CreateComponent29"
remove_body "RemoveBody9"
named bodies: "PCB Mount", "Base 1", "Lock Base", "Base 2"

design "PCB mount" references "PCB1"
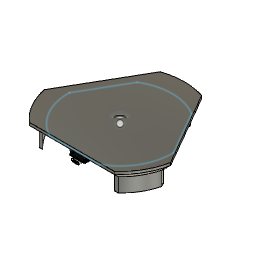
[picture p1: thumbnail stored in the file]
base_feature "Base Feature"
component_insert "Component Insert"
step "Context"
position "Position1"

design "R servo horn"
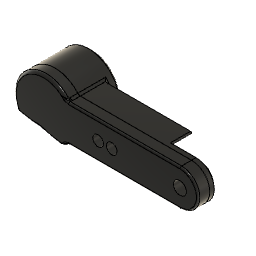
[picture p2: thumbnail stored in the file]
base_feature "Base Feature3"
base_feature "Base Feature1" bodies "R Back"
copy_paste_bodies "CutPasteBodies"
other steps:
base_feature "Base Feature2" bodies "R Front"
named bodies: "R Back", "R Front"

design "KBRM_05_1"
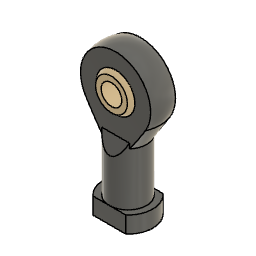
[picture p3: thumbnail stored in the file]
description: STEP AP214
description: PART-2025_05_17_16_26_50_0214-DESC
part number: 2025_05_17_16_26_50_0214
description: PART-2025_05_17_16_26_50_0230-DESC
part number: 2025_05_17_16_26_50_0230
base_feature "Base Feature1"
base_feature "Base Feature1"
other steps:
create_component "CreateComponent1"
create_component "CreateComponent2"

design "KBRM_10_2"
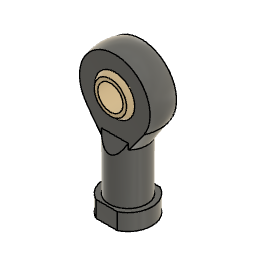
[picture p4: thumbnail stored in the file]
description: STEP AP214
description: PART-2025_05_17_16_36_44_0024-DESC
part number: 2025_05_17_16_36_44_0024
description: PART-2025_05_17_16_36_44_0039-DESC
part number: 2025_05_17_16_36_44_0039
base_feature "Base Feature1"
base_feature "Base Feature1"
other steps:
create_component "CreateComponent1"
create_component "CreateComponent2"

design "Ball joint"
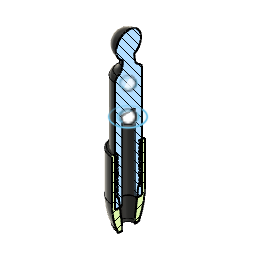
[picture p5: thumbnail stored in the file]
description: STEP AP214
part number: 2025_05_17_16_39_25_0877
base_feature "Base Feature2"
base_feature "Base Feature1"
sketch "Sketch1" plane through (0, 0, 0) normal (0, 0, 1) x axis (1, 0, 0)
  circle C1 centre (0, 0) radius 5.4918
  point P11 (0, 0)
  dimension "d2" distance P11 = 5
sketch "Sketch2" plane through (0, 0, 14.7) normal (0, 0, 1) x axis (-1, 0, 0)
  line L1 (6.3509, 0) -> (3.1754, -5.5)
  line L2 (3.1754, 5.5) -> (6.3509, 0)
  line L3 (-3.1754, 5.5) -> (3.1754, 5.5)
  line L4 (-6.3509, 0) -> (-3.1754, 5.5)
  line L5 (-3.1754, -5.5) -> (-6.3509, 0)
  line L6 (3.1754, -5.5) -> (-3.1754, -5.5)
  circle C1 centre (0, 0) radius 4
  circle C2 centre (0, 0) radius 5.4918
  circle C3 centre (0, 0) radius 8.4893
  concentric C2 C3
extrude "Extrude1" add sketch "Sketch2" profile of C1 C2 to an object
extrude "Extrude2" cut sketch "Sketch2" profile of L1 L2 L3 L4 L5 L6 C2 C3 against normal blind 18.267 named "d3_2"
sketch "Sketch3" plane through (0, 0, 0) normal (0, 0, -1) x axis (1, 0, 0)
  circle C1 centre (0, 0) radius 5.4918
  circle C2 centre (0, 0) radius 3
  circle C3 centre (0, 0) radius 2.55
  concentric C1 C3
  dimension "d5_2" diameter C3 = 5.1
extrude "Extrude3" cut sketch "Sketch3" profile of C3 against normal blind 11.8 named "d6_2"
sketch "Sketch4" plane through (0, 0, 0) normal (1, 0, 0) x axis (0, 1, 0)
  line L1 (2.7607, 21.4416) -> (2.9918, 19.2432)
  line L2 (-2.9918, 19.2432) -> (-2.7607, 21.4416)
  line L3 (-5.4918, 0) -> (-5.4918, 16.7432)
  line L4 (-3, 0) -> (-5.4918, 0)
  line L5 (-2.55, 0.45) -> (-3, 0)
  line L6 (-2.55, 11.8) -> (-2.55, 0.45)
  line L7 (-2.5, 11.8) -> (-2.55, 11.8)
  line L8 (-2.5, 12) -> (-2.5, 11.8)
  line L9 (0, 13.4434) -> (-2.5, 12)
  line L10 (2.5, 12) -> (0, 13.4434)
  line L11 (2.5, 11.8) -> (2.5, 12)
  line L12 (2.55, 11.8) -> (2.5, 11.8)
  line L13 (2.55, 0.45) -> (2.55, 11.8)
  line L14 (3, 0) -> (2.55, 0.45)
  line L15 (5.4918, 0) -> (3, 0)
  line L16 (5.4918, 16.7432) -> (5.4918, 0)
  line L17 (2.2547, 21.4732) -> (2.4945, 19.1909)
  arc A1 centre (0, 25.7) radius 5.075 clockwise from (0, 30.775) to (2.7607, 21.4416)
  arc A2 centre (0, 25.7) radius 5.075 clockwise from (-2.7607, 21.4416) to (0, 30.775)
  arc A3 centre (-5.7854, 19.5368) radius 2.809 between (-5.4918, 16.7432) and (-2.9918, 19.2432)
  arc A4 centre (5.7854, 19.5368) radius 2.809 between (2.9918, 19.2432) and (5.4918, 16.7432)
  circle C1 centre (0, 25.7) radius 5.075
  arc A5 centre (5.7854, 19.5368) radius 3.309 clockwise from (5.4918, 16.2409) to (2.4945, 19.1909)
  point P3 (2.7607, 21.4416)
  point P29 (5.4918, 16.2409)
  concentric A1 C1
  coincident P3 C1
  concentric A4 A5
  coincident L16 P29
revolve "Revolve1" sketch "Sketch4" AlongAngle 360 named "d9_2"
fillet "Fillet1" radius 0.4 named "d11_2"
fillet "Fillet2" radius 2 named "d13_2"
extrude "Extrude4" add sketch "Reconstructed-Sketch5" blind 10 second side blind 2.2
extrude "Extrude5" add sketch "Reconstructed-Sketch6" + "Reconstructed-Sketch7" blind 10 second side blind 2
chamfer "Chamfer1" distance 0.45
copy_paste_bodies "CopyPasteBodies1"
sketch "Sketch5" plane through (0, 0, -10) normal (0, 0, -1) x axis (1, 0, 0)
  circle C1 centre (0, 0) radius 5.4918
  circle C2 centre (0, 0) radius 3
  circle C3 centre (0, 0) radius 2.55
  circle C4 centre (0, 0) radius 3
extrude "Extrude6" add sketch "Sketch5" along normal blind 16 and against normal blind 3.9
sketch "Sketch6" plane through (0, 0, -26) normal (0, 0, -1) x axis (1, 0, 0)
  circle C1 centre (0, 0) radius 2.55
  circle C2 centre (0, 0) radius 5
  circle C3 centre (0, 0) radius 6
  circle C4 centre (0, 0) radius 5.4918
  point P1 (0, 0)
  point P3 (0, 0)
  coincident P1 P3
  dimension "d20" diameter C2 = 10
  dimension "d21" = 1
extrude "Extrude7" cut sketch "Sketch6" profile of C2 C3 C4 against normal blind 16
thread "Thread1" ThreadOffset 0 ThreadLength 10
sketch "Sketch7" plane through (0, 0, -26) normal (0, 0, -1) x axis (1, 0, 0)
  curve K1 (-2.1933, -4.4186) -> (-2.4523, 3.4377)
  curve K2 (2.4523, 3.4377) -> (2.1933, -4.4186)
  arc A1 centre (0, 0) radius 4.933 clockwise from (2.1933, -4.4186) to (-2.1933, -4.4186)
  arc A2 centre (0, 0) radius 4.2228 clockwise from (-2.4523, 3.4377) to (2.4523, 3.4377)
  circle C1 centre (0, 0) radius 2.55
  circle C2 centre (0, 0) radius 4.2228
  point P6 (2.4523, 3.4377)
  concentric A1 C2
  coincident P6 C2
extrude "Extrude8" add sketch "Sketch7" profile of A2 C1 C2 along normal blind 8
chamfer "Chamfer3" distance 1 distance 8
sketch "Sketch8" plane through (0, 0, -34) normal (0, 0, 1) x axis (1, 0, 0)
  line L1 (-0.3797, 5.6043) -> (0.3797, 5.6043)
  line L2 (-0.3797, -5.6043) -> (-0.3797, 5.6043)
  line L3 (0.3797, -5.6043) -> (-0.3797, -5.6043)
  line L4 (0.3797, 5.6043) -> (0.3797, -5.6043)
  line L5 (-0.3797, -5.6043) -> (0.3797, 5.6043)
  line L6 (0.3797, -5.6043) -> (-0.3797, 5.6043)
  line L7 (1.2319, 1.7802) -> (-1.2619, 1.8553)
  circle C1 centre (0, 0) radius 2.55
  circle C2 centre (0, 0) radius 3.2228
  point P6 (0, 0)
  point P1 (0, 0)
  horizontal L1
  perpendicular L1 L2
  parallel L1 L3
  parallel L2 L4
  coincident L5 P6
  coincident L6 P6
  coincident P1 P6
extrude "Extrude9" cut sketch "Sketch8" profile of L1 L2 L4 C1 C2 along normal blind 10
circular_pattern "C-Pattern1" TotalAngle 360
sketch "Sketch9" plane through (0, 0, 0) normal (0, 1, 0) x axis (1, 0, 0)
  line L1 (2.4945, -19.1909) -> (2.3146, -20.9023)
  line L2 (5.4918, 10) -> (5.4918, -14.7488)
  line L3 (4.933, 10) -> (5.4918, 10)
  line L4 (4.933, 10.1542) -> (4.933, 10)
  line L5 (4.2227, 10.5642) -> (4.933, 10.1542)
  line L6 (4.2227, 10.8108) -> (4.2227, 10.5642)
  line L7 (4.933, 11.2208) -> (4.2227, 10.8108)
  line L8 (4.933, 11.4042) -> (4.933, 11.2208)
  line L9 (4.2227, 11.8142) -> (4.933, 11.4042)
  line L10 (4.2227, 12.0608) -> (4.2227, 11.8142)
  line L11 (4.933, 12.4708) -> (4.2227, 12.0608)
  line L12 (4.933, 12.6542) -> (4.933, 12.4708)
  line L13 (4.2227, 13.0642) -> (4.933, 12.6542)
  line L14 (4.2227, 13.3108) -> (4.2227, 13.0642)
  line L15 (4.933, 13.7208) -> (4.2227, 13.3108)
  line L16 (4.933, 13.9042) -> (4.933, 13.7208)
  line L17 (4.2227, 14.3142) -> (4.933, 13.9042)
  line L18 (4.2227, 14.5608) -> (4.2227, 14.3142)
  line L19 (4.933, 14.9708) -> (4.2227, 14.5608)
  line L20 (4.933, 15.1542) -> (4.933, 14.9708)
  line L21 (4.2227, 15.5642) -> (4.933, 15.1542)
  line L22 (4.2227, 15.8108) -> (4.2227, 15.5642)
  line L23 (4.933, 16.2208) -> (4.2227, 15.8108)
  line L24 (4.933, 16.4042) -> (4.933, 16.2208)
  line L25 (4.2227, 16.8142) -> (4.933, 16.4042)
  line L26 (4.2227, 17.0608) -> (4.2227, 16.8142)
  line L27 (4.933, 17.4708) -> (4.2227, 17.0608)
  line L28 (4.933, 17.6542) -> (4.933, 17.4708)
  line L29 (4.2227, 18.0642) -> (4.933, 17.6542)
  line L30 (4.2227, 18.3108) -> (4.2227, 18.0642)
  line L31 (4.933, 18.7208) -> (4.2227, 18.3108)
  line L32 (4.933, 18.9042) -> (4.933, 18.7208)
  line L33 (4.2227, 19.3142) -> (4.933, 18.9042)
  line L34 (4.2227, 19.5608) -> (4.2227, 19.3142)
  line L35 (4.933, 19.9708) -> (4.2227, 19.5608)
  line L36 (4.933, 20.1542) -> (4.933, 19.9708)
  line L37 (4.2227, 20.5642) -> (4.933, 20.1542)
  line L38 (4.2227, 20.8108) -> (4.2227, 20.5642)
  line L39 (4.933, 21.2208) -> (4.2227, 20.8108)
  line L40 (4.933, 21.4042) -> (4.933, 21.2208)
  line L41 (4.2227, 21.8142) -> (4.933, 21.4042)
  line L42 (4.2227, 22.0608) -> (4.2227, 21.8142)
  line L43 (4.933, 22.4708) -> (4.2227, 22.0608)
  line L44 (4.933, 22.6542) -> (4.933, 22.4708)
  line L45 (4.2227, 23.0642) -> (4.933, 22.6542)
  line L46 (4.2227, 23.3108) -> (4.2227, 23.0642)
  line L47 (4.933, 23.7208) -> (4.2227, 23.3108)
  line L48 (4.933, 23.9042) -> (4.933, 23.7208)
  line L49 (4.2227, 24.3142) -> (4.933, 23.9042)
  line L50 (4.2227, 24.5608) -> (4.2227, 24.3142)
  line L51 (4.933, 24.9708) -> (4.2227, 24.5608)
  line L52 (4.933, 25.1542) -> (4.933, 24.9708)
  line L53 (4.2227, 25.5642) -> (4.933, 25.1542)
  line L54 (4.2227, 25.8108) -> (4.2227, 25.5642)
  line L55 (4.5505, 26) -> (4.2227, 25.8108)
  line L56 (4.2228, 26) -> (4.5505, 26)
  line L57 (3.2228, 34) -> (4.2228, 26)
  line L58 (2.55, 34) -> (3.2228, 34)
  line L59 (2.55, -1.8) -> (2.55, 34)
  line L60 (-2.55, -1.8) -> (2.55, -1.8)
  line L61 (-2.55, 34) -> (-2.55, -1.8)
  line L62 (-3.2228, 34) -> (-2.55, 34)
  line L63 (-4.2228, 26) -> (-3.2228, 34)
  line L64 (-4.5505, 26) -> (-4.2228, 26)
  line L65 (-4.933, 25.7792) -> (-4.5505, 26)
  line L66 (-4.933, 25.5958) -> (-4.933, 25.7792)
  line L67 (-4.2227, 25.1858) -> (-4.933, 25.5958)
  line L68 (-4.2227, 24.9392) -> (-4.2227, 25.1858)
  line L69 (-4.933, 24.5292) -> (-4.2227, 24.9392)
  line L70 (-4.933, 24.3458) -> (-4.933, 24.5292)
  line L71 (-4.2227, 23.9358) -> (-4.933, 24.3458)
  line L72 (-4.2227, 23.6892) -> (-4.2227, 23.9358)
  line L73 (-4.933, 23.2792) -> (-4.2227, 23.6892)
  line L74 (-4.933, 23.0958) -> (-4.933, 23.2792)
  line L75 (-4.2227, 22.6858) -> (-4.933, 23.0958)
  line L76 (-4.2227, 22.4392) -> (-4.2227, 22.6858)
  line L77 (-4.933, 22.0292) -> (-4.2227, 22.4392)
  line L78 (-4.933, 21.8458) -> (-4.933, 22.0292)
  line L79 (-4.2227, 21.4358) -> (-4.933, 21.8458)
  line L80 (-4.2227, 21.1892) -> (-4.2227, 21.4358)
  line L81 (-4.933, 20.7792) -> (-4.2227, 21.1892)
  line L82 (-4.933, 20.5958) -> (-4.933, 20.7792)
  line L83 (-4.2227, 20.1858) -> (-4.933, 20.5958)
  line L84 (-4.2227, 19.9392) -> (-4.2227, 20.1858)
  line L85 (-4.933, 19.5292) -> (-4.2227, 19.9392)
  line L86 (-4.933, 19.3458) -> (-4.933, 19.5292)
  line L87 (-4.2227, 18.9358) -> (-4.933, 19.3458)
  line L88 (-4.2227, 18.6892) -> (-4.2227, 18.9358)
  line L89 (-4.933, 18.2792) -> (-4.2227, 18.6892)
  line L90 (-4.933, 18.0958) -> (-4.933, 18.2792)
  line L91 (-4.2227, 17.6858) -> (-4.933, 18.0958)
  line L92 (-4.2227, 17.4392) -> (-4.2227, 17.6858)
  line L93 (-4.933, 17.0292) -> (-4.2227, 17.4392)
  line L94 (-4.933, 16.8458) -> (-4.933, 17.0292)
  line L95 (-4.2227, 16.4358) -> (-4.933, 16.8458)
  line L96 (-4.2227, 16.1892) -> (-4.2227, 16.4358)
  line L97 (-4.933, 15.7792) -> (-4.2227, 16.1892)
  line L98 (-4.933, 15.5958) -> (-4.933, 15.7792)
  line L99 (-4.2227, 15.1858) -> (-4.933, 15.5958)
  line L100 (-4.2227, 14.9392) -> (-4.2227, 15.1858)
  line L101 (-4.933, 14.5292) -> (-4.2227, 14.9392)
  line L102 (-4.933, 14.3458) -> (-4.933, 14.5292)
  line L103 (-4.2227, 13.9358) -> (-4.933, 14.3458)
  line L104 (-4.2227, 13.6892) -> (-4.2227, 13.9358)
  line L105 (-4.933, 13.2792) -> (-4.2227, 13.6892)
  line L106 (-4.933, 13.0958) -> (-4.933, 13.2792)
  line L107 (-4.2227, 12.6858) -> (-4.933, 13.0958)
  line L108 (-4.2227, 12.4392) -> (-4.2227, 12.6858)
  line L109 (-4.933, 12.0292) -> (-4.2227, 12.4392)
  line L110 (-4.933, 11.8458) -> (-4.933, 12.0292)
  line L111 (-4.2227, 11.4358) -> (-4.933, 11.8458)
  line L112 (-4.2227, 11.1892) -> (-4.2227, 11.4358)
  line L113 (-4.933, 10.7792) -> (-4.2227, 11.1892)
  line L114 (-4.933, 10.5958) -> (-4.933, 10.7792)
  line L115 (-4.2227, 10.1858) -> (-4.933, 10.5958)
  line L116 (-4.2227, 10) -> (-4.2227, 10.1858)
  line L117 (-5.4918, 10) -> (-4.2227, 10)
  line L118 (-5.4918, -14.7488) -> (-5.4918, 10)
  line L119 (-2.3146, -20.9023) -> (-2.4945, -19.1909)
  line L120 (5.4918, 28.8525) -> (5.4918, 10)
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  point P15 (5.4918, 10)
  point P136 (5.4918, 10)
  point P1 (0, 0)
  point P140 (0, 0)
  point P142 (5.4918, 10)
  point P69 (4.2228, 26)
  point P145 (4.2228, 26)
  point P71 (2.55, 34)
  point P149 (2.55, 34)
  point P152 (5.4918, 26.0479)
  coincident P15 P136
  perpendicular L3 L120
  coincident P1 P140
  coincident P15 P142
  coincident P69 P145
  coincident P71 P149
  coincident L120 P152
  dimension "d34" = -0.2
revolve "Revolve2" sketch "Sketch9" AlongAngle 360
sketch "Sketch1" plane through (0, 0, 0) normal (1, 0, 0) x axis (0, 1, 0)
  line L1 (5, 16) -> (5, 0)
  line L2 (2.5, 16) -> (5, 16)
  line L3 (2.5, 31.889) -> (2.5, 16)
  line L4 (3.8537, 31.889) -> (2.5, 31.889)
  line L5 (8, 21.4301) -> (3.8537, 31.889)
  line L6 (8, 0) -> (8, 21.4301)
  line L7 (5, 0) -> (8, 0)
  line L8 (5, 0) -> (0, 0)
  line L9 (0, 54.5517) -> (0, 0)
  point P1 (0, 0)
  point P9 (0, 0)
  point P10 (0, 0)
  point P2 (5, 0)
  point P3 (5, 16)
  point P8 (8, 0)
  vertical L1
  perpendicular L1 L2
  perpendicular L2 L3
  perpendicular L3 L4
  perpendicular L4 L6
  horizontal L7
  coincident P1 P9
  horizontal L8
  coincident P1 P10
  perpendicular L8 L9
  dimension "d1" distance P2 P3 = 16
  dimension "d2" distance P1 L1 = 5
  dimension "d3" distance L3 L9 = 2.5
  dimension "d4" distance P2 P8 = 3
revolve "Revolve1" sketch "Sketch1" AlongAngle 360
thread "Thread1" ThreadOffset 0 ThreadLength 10
chamfer "Chamfer1" distance 11.019 distance 1.47
offset_faces "OffsetFaces1" distance -3.6
offset_faces "OffsetFaces2" distance -1.3
offset_faces "OffsetFaces3" distance -1
fillet "Fillet1" radius 26.196
fillet "Fillet2" radius 0.5
fillet "Fillet3" radius 0.5
sketch "Sketch10" plane through (0, 0, -10) normal (0, 0, -1) x axis (1, 0, 0)
  circle C1 centre (0, 0) radius 5.4918
  circle C2 centre (0, 0) radius 3
  circle C3 centre (0, 0) radius 2.55
  circle C4 centre (0, 0) radius 3
extrude "Extrude10" add sketch "Sketch10" against normal blind 1.14 and along normal blind 20
chamfer "Chamfer4" distance 0.75
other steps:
base_feature "Base Feature3" bodies "Lock Base"
create_component "CreateComponent1"
named bodies: "Lock Base"

design "fab dev board 2" references "Fab Board"
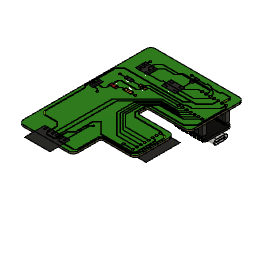
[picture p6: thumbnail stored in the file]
external_derived "Outline(Sketch2)"
sketch "Outline" plane through (0, 0, 0) normal (0, 0, 1) x axis (1, 0, 0)
step sketch "Outline(Sketch2)"
canvas "Canvas1" bodies "Board"
canvas "Canvas2" bodies "Board"
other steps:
derived_base_feature "Outline(Sketch2)"
base_feature "Base Feature1"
